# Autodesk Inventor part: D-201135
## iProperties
Created: 2007-10
Part Number: D-201135
Document SubType Name: Modeling
Designer: TH
Density: 7.85 g/cm^3
Mass: 34.6613 g
Surface Area: 33.8 cm^2
Volume: 4.41545 cm^3
Material: Steel
Description: PIVOT PLATE
Component Category: Lower Component
Author: TH
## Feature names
1. Extrusion1
2. Hole1
3. Hole2
